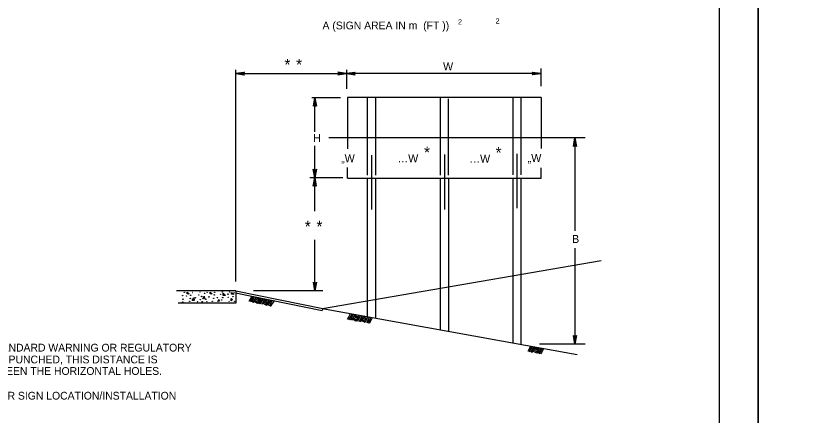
# Model space of a CAD drawing. Extents: x 644358 to 648627, y 294594 to 295782.
# Drawn here: x 645753.8 to 646056.9, y 294889.9 to 295044.1 of the extents above; entities that cross this region are included whole.
import ezdxf

# ---------------------------------------------------------------- set-up
doc = ezdxf.new("R2010")
doc.units = 0
for name, color, linetype in [('1', 7, 'Continuous'), ('2', 7, 'Continuous'), ('3', 7, 'Continuous'), ('4', 7, 'Continuous'), ('PLT-BNDY', 7, 'Continuous')]:
    doc.layers.add(name, color=color, linetype=linetype)

msp = doc.modelspace()

# ---------------------------------------------------------------- linework, layer by layer
at = {"layer": '1'}
msp.add_line((646025.31, 294608.63), (646025.31, 295172.63), dxfattribs=at)
for points in [[(645819.94, 294936.74), (645819.94, 294937.36), (645820.69, 294936.74)], [(645822.44, 294935.24), (645822.56, 294934.11), (645821.81, 294934.11)], [(645826.44, 294935.86), (645826.56, 294934.99), (645825.94, 294934.86)], [(645828.81, 294936.74), (645828.81, 294937.36), (645829.56, 294936.74)], [(645833.81, 294936.11), (645833.81, 294936.99), (645834.69, 294936.11)], [(645837.06, 294936.61), (645837.06, 294937.24), (645838.06, 294936.61)], [(645832.19, 294934.61), (645832.31, 294933.86), (645831.69, 294933.74)], [(645836.94, 294933.99), (645836.94, 294934.99), (645837.44, 294934.49)]]:
    msp.add_lwpolyline(points, close=True, dxfattribs=at)
for centre, radius in [((645818.2, 294936.03), 0.0979), ((645818.85, 294937.34), 0.056), ((645819.68, 294935.92), 0.056), ((645821.27, 294936.19), 0.0979), ((645821.95, 294937.25), 0.056), ((645823.02, 294935.22), 0.0979), ((645824.38, 294936.23), 0.056), ((645824.89, 294937.37), 0.056), ((645825.52, 294935.7), 0.0979), ((645826.64, 294936.91), 0.0979), ((645827.62, 294937.34), 0.056), ((645828.3, 294935.56), 0.0979), ((645830.39, 294936.34), 0.0979), ((645830.55, 294937.3), 0.056), ((645831.62, 294935.27), 0.0979), ((645832.76, 294936.55), 0.056), ((645833.49, 294937.42), 0.056), ((645833.67, 294935.3), 0.0979), ((645835.66, 294936.61), 0.0979), ((645835.78, 294935.33), 0.056), ((645836.22, 294937.39), 0.056), ((645837.59, 294935.63), 0.0979), ((645838.06, 294937.36), 0.056), ((645818.16, 294933.61), 0.056), ((645818.32, 294934.67), 0.0979), ((645820.87, 294933.81), 0.056), ((645821.13, 294934.94), 0.0979), ((645823.85, 294933.66), 0.056), ((645824.99, 294934.48), 0.0979), ((645825.72, 294933.66), 0.0979), ((645827.1, 294934.67), 0.0979), ((645827.53, 294933.69), 0.056), ((645829.65, 294933.81), 0.056), ((645830.2, 294934.99), 0.0979), ((645833.22, 294934.33), 0.0979), ((645836.13, 294933.74), 0.056), ((645838.24, 294933.86), 0.056)]:
    msp.add_circle(centre, radius, dxfattribs=at)
at = {"layer": '2'}
for p, q in [((645881.81, 295012.49), (645881.81, 294992.74)), ((645956.56, 295012.49), (645881.81, 295012.49)), ((645889.44, 295012.49), (645889.44, 294982.49)), ((645892.56, 295012.49), (645892.56, 294982.49)), ((645917.56, 295012.49), (645917.56, 294982.49)), ((645920.69, 295011.99), (645920.69, 294982.49)), ((645945.56, 295012.49), (645945.56, 294982.61)), ((645948.69, 295012.49), (645948.69, 294982.61)), ((645956.56, 295012.49), (645956.56, 294992.86)), ((645891.06, 294990.24), (645891.06, 294969.24)), ((645919.19, 294990.49), (645919.19, 294969.24)), ((645947.19, 294990.74), (645947.19, 294969.74)), ((645881.81, 294981.36), (645881.81, 294985.49)), ((645956.56, 294981.36), (645956.56, 294985.36)), ((645881.81, 294981.36), (645956.56, 294981.36)), ((645889.44, 294981.49), (645889.44, 294927.99)), ((645892.56, 294981.49), (645892.56, 294927.36)), ((645917.56, 294981.49), (645917.56, 294922.92)), ((645920.81, 294981.36), (645920.81, 294922.33)), ((645945.56, 294981.36), (645945.56, 294917.86)), ((645948.69, 294981.49), (645948.69, 294917.36)), ((645872.19, 294931.11), (645979.69, 294949.61)), ((645838.69, 294937.86), (645815.81, 294937.86)), ((645838.56, 294937.11), (645872.06, 294930.24)), ((645838.69, 294937.86), (645872.31, 294931.11)), ((645838.69, 294937.86), (645838.69, 294933.11)), ((645844.69, 294935.61), (645843.69, 294933.74)), ((645845.31, 294935.61), (645844.19, 294933.61)), ((645845.81, 294935.49), (645844.69, 294933.49)), ((645846.44, 294935.36), (645845.31, 294933.36)), ((645847.81, 294934.36), (645846.44, 294935.36)), ((645838.69, 294933.11), (645816.44, 294933.11)), ((645845.56, 294933.36), (645845.31, 294933.49)), ((645847.06, 294932.99), (645845.56, 294933.86)), ((645847.31, 294933.49), (645845.81, 294934.24)), ((645847.56, 294933.99), (645846.06, 294934.86)), ((645848.19, 294934.99), (645847.06, 294932.99)), ((645848.81, 294934.86), (645847.56, 294932.86)), ((645848.19, 294934.86), (645847.81, 294934.99)), ((645849.31, 294934.74), (645848.06, 294932.74)), ((645849.81, 294934.61), (645848.69, 294932.61)), ((645850.44, 294932.36), (645848.94, 294933.11)), ((645850.69, 294932.74), (645849.19, 294933.61)), ((645850.94, 294933.24), (645849.44, 294934.11)), ((645851.31, 294933.74), (645849.81, 294934.49)), ((645851.56, 294934.11), (645850.31, 294932.24)), ((645852.06, 294934.11), (645850.94, 294932.24)), ((645851.56, 294934.11), (645851.31, 294934.24)), ((645852.69, 294934.11), (645851.56, 294931.99)), ((645853.31, 294933.86), (645851.94, 294931.86)), ((645872.31, 294931.11), (645872.06, 294930.24)), ((645872.19, 294931.11), (645970.44, 294913.36)), ((645882.81, 294928.86), (645881.69, 294926.86)), ((645883.44, 294928.74), (645882.19, 294926.74)), ((645883.81, 294928.61), (645882.81, 294926.61)), ((645884.44, 294928.49), (645883.31, 294926.61)), ((645883.56, 294926.61), (645883.44, 294926.61)), ((645885.06, 294926.24), (645883.56, 294927.11)), ((645885.31, 294926.61), (645883.81, 294927.61)), ((645885.69, 294927.24), (645884.19, 294928.11)), ((645885.94, 294927.61), (645884.44, 294928.49)), ((645886.31, 294928.11), (645885.06, 294926.24)), ((645886.69, 294928.11), (645885.69, 294926.11)), ((645886.19, 294928.11), (645885.94, 294928.24)), ((645887.31, 294928.11), (645886.31, 294925.99)), ((645887.94, 294927.99), (645886.69, 294925.99)), ((645888.56, 294925.61), (645887.06, 294926.49)), ((645888.81, 294926.11), (645887.31, 294926.86)), ((645889.06, 294926.61), (645887.56, 294927.36)), ((645889.31, 294926.99), (645887.94, 294927.86)), ((645889.56, 294927.61), (645888.44, 294925.61)), ((645890.19, 294927.49), (645889.06, 294925.49)), ((645889.56, 294927.49), (645889.31, 294927.74)), ((645890.81, 294927.36), (645889.56, 294925.36)), ((645891.19, 294927.24), (645890.19, 294925.24)), ((645952.44, 294916.36), (645951.31, 294914.49)), ((645952.94, 294916.24), (645951.81, 294914.36)), ((645953.56, 294916.11), (645952.44, 294914.24)), ((645954.06, 294916.11), (645952.94, 294914.11)), ((645953.19, 294914.11), (645952.94, 294914.24)), ((645954.81, 294913.86), (645953.31, 294914.61)), ((645954.94, 294914.36), (645953.56, 294915.11)), ((645955.31, 294914.74), (645953.81, 294915.61)), ((645955.44, 294915.24), (645953.94, 294916.11)), ((645955.81, 294915.74), (645954.81, 294913.74)), ((645956.44, 294915.74), (645955.31, 294913.74)), ((645955.81, 294915.74), (645955.44, 294915.86)), ((645956.94, 294915.61), (645955.81, 294913.49)), ((645957.44, 294915.49), (645956.44, 294913.49))]:
    msp.add_line(p, q, dxfattribs=at)
at = {"layer": '4'}
for p, q in [((645838.69, 294941.49), (645838.69, 295023.24)), ((645881.44, 295023.24), (645881.44, 295015.86)), ((645956.44, 295023.74), (645956.44, 295016.86)), ((645838.69, 295021.74), (645881.44, 295021.74)), ((645956.44, 295021.74), (645881.44, 295021.74)), ((645879.06, 295012.36), (645868.06, 295012.36)), ((645869.19, 294999.24), (645869.19, 295012.36)), ((645973.44, 294996.99), (645874.56, 294996.99)), ((645969.56, 294996.99), (645969.56, 294960.99)), ((645869.19, 294981.74), (645869.19, 294993.86)), ((645879.94, 294981.49), (645867.19, 294981.49)), ((645869.19, 294981.36), (645869.19, 294981.74)), ((645869.19, 294968.61), (645869.19, 294981.74)), ((645869.19, 294937.86), (645869.19, 294957.61)), ((645969.56, 294954.36), (645969.56, 294917.36)), ((645872.31, 294937.86), (645845.56, 294937.86)), ((645973.44, 294917.36), (645955.94, 294917.36))]:
    msp.add_line(p, q, dxfattribs=at)
for points in [[(645841.81, 295021.24), (645841.69, 295021.49), (645838.69, 295021.74), (645841.81, 295021.24), (645842.06, 295021.24), (645838.69, 295021.74), (645841.69, 295021.86), (645841.81, 295022.11), (645838.69, 295021.74), (645842.06, 295022.24), (645841.81, 295022.11)], [(645878.31, 295021.24), (645878.44, 295021.49), (645881.44, 295021.74), (645878.31, 295021.24), (645878.06, 295021.24), (645881.44, 295021.74), (645878.44, 295021.86), (645878.31, 295022.11), (645881.44, 295021.74), (645878.06, 295022.24), (645878.31, 295022.11)], [(645884.56, 295021.24), (645884.44, 295021.49), (645881.44, 295021.74), (645884.56, 295021.24), (645884.81, 295021.24), (645881.44, 295021.74), (645884.44, 295021.86), (645884.56, 295022.11), (645881.44, 295021.74), (645884.81, 295022.24), (645884.56, 295022.11)], [(645953.19, 295022.11), (645953.31, 295021.86), (645956.44, 295021.74), (645953.19, 295022.11), (645953.06, 295022.36), (645956.44, 295021.74), (645953.31, 295021.61), (645953.19, 295021.36), (645956.44, 295021.74), (645953.06, 295021.24), (645953.19, 295021.36)], [(645868.81, 295009.24), (645869.06, 295009.36), (645869.19, 295012.36), (645868.81, 295009.24), (645868.69, 295009.11), (645869.19, 295012.36), (645869.44, 295009.36), (645869.69, 295009.24), (645869.19, 295012.36), (645869.81, 295009.11), (645869.69, 295009.24)], [(645969.19, 294993.86), (645969.44, 294993.99), (645969.56, 294996.99), (645969.19, 294993.86), (645968.94, 294993.61), (645969.56, 294996.99), (645969.69, 294993.99), (645969.94, 294993.86), (645969.56, 294996.99), (645970.19, 294993.61), (645969.94, 294993.86)], [(645869.56, 294984.61), (645869.31, 294984.49), (645869.19, 294981.49), (645869.56, 294984.61), (645869.81, 294984.86), (645869.19, 294981.49), (645869.06, 294984.49), (645868.81, 294984.61), (645869.19, 294981.49), (645868.56, 294984.86), (645868.81, 294984.61)], [(645868.69, 294978.36), (645868.94, 294978.49), (645869.19, 294981.61), (645868.69, 294978.36), (645868.56, 294978.24), (645869.19, 294981.61), (645869.31, 294978.49), (645869.56, 294978.36), (645869.19, 294981.61), (645869.69, 294978.24), (645869.56, 294978.36)], [(645869.69, 294940.99), (645869.44, 294940.86), (645869.19, 294937.86), (645869.69, 294940.99), (645869.81, 294941.24), (645869.19, 294937.86), (645869.06, 294940.86), (645868.81, 294940.99), (645869.19, 294937.86), (645868.69, 294941.24), (645868.81, 294940.99)], [(645969.94, 294920.49), (645969.81, 294920.36), (645969.56, 294917.36), (645969.94, 294920.49), (645970.19, 294920.61), (645969.56, 294917.36), (645969.44, 294920.36), (645969.19, 294920.49), (645969.56, 294917.36), (645968.94, 294920.61), (645969.19, 294920.49)]]:
    msp.add_lwpolyline(points, dxfattribs=at)
at = {"layer": 'PLT-BNDY'}
for points in [[(645199.31, 295187.63), (646040.31, 295187.63), (646040.31, 294593.63), (645199.31, 294593.63)], [(646040.31, 295187.63), (646881.31, 295187.63), (646881.31, 294593.63), (646040.31, 294593.63)]]:
    msp.add_lwpolyline(points, close=True, dxfattribs=at)

# ---------------------------------------------------------------- texts
at = {"layer": '3'}
for s, height, p in [('„W', 3.09, (645879.31, 294987.49)), ('…W', 3.09, (645901.06, 294987.49)), ('…W', 3.09, (645928.81, 294987.36)), ('„W', 3.09, (645951.31, 294987.61)), ('B', 3.09, (645968.44, 294956.36)), ('SEE SHEET 9 OF 9 FOR SIGN LOCATION/INSTALLATION', 3, (645708.03, 294895.91))]:
    msp.add_text(s, height=height, dxfattribs=at).set_placement(p)
at = {"layer": '4'}
for s, height, p in [('A (SIGN AREA IN m  (FT ))', 3.005, (645872.14, 295038.82)), ('2', 2, (645924.43, 295040.71)), ('2', 2, (645938.92, 295041.08)), ('*', 4.45, (645857.44, 295022.99)), ('*', 4.45, (645861.94, 295022.99)), ('W', 3.09, (645918.66, 295023.02)), ('H', 3.09, (645868.56, 294995.36)), ('*', 4.45, (645911.31, 294989.11)), ('*', 4.45, (645938.94, 294988.99)), ('*', 4.45, (645865.31, 294960.49)), ('*', 4.45, (645869.81, 294960.49)), ('WHEN ERECTING STANDARD WARNING OR REGULATORY', 3, (645707.97, 294914.46)), ('SIGNS THAT ARE PREPUNCHED, THIS DISTANCE IS', 3, (645708.2, 294909.9)), ('THE DISTANCE BETWEEN THE HORIZONTAL HOLES.', 3, (645707.91, 294905.45))]:
    msp.add_text(s, height=height, dxfattribs=at).set_placement(p)

doc.saveas('drawing.dxf')
